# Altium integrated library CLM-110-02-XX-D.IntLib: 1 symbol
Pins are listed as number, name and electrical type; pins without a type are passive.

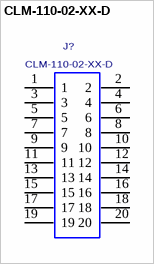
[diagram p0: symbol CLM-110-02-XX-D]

## CLM-110-02-XX-D
designator J?
Low profile Socket Strip, 1 mm Pitch, 20 Pins.; MANUFACTURER: SAMTEC
footprint CLM-110-02-XX-D
pins: 1, 2, 3, 4, 5, 6, 7, 8, 9, 10, 11, 12, 13, 14, 15, 16, 17, 18, 19, 20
